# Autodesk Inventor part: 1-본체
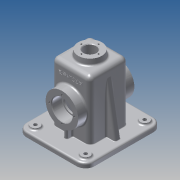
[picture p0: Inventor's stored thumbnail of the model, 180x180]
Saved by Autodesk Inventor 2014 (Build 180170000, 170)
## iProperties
Created: 2015-12
Part Number: 1-본체
Material: 알루미늄 6061
Document SubType Name: Modeling
Designer: Administrator
Density: 2.71 g/cm^3
Appearance: 알루미늄 - 평지
Mass: 803.266 g
Surface Area: 909.178 cm^2
Volume: 296.408 cm^3
Author: Administrator
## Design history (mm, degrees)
sketch "스케치1"
  geometry: L1 (-50, -57.5)-(50, -57.5); L2 (65, -42.5)-(65, 42.5); L3 (50, 57.5)-(-50, 57.5); L4 (-65, 42.5)-(-65, -42.5); A1 r 15 centre (-50, 42.5) between (-50, 57.5) and (-65, 42.5); A2 r 15 centre (-50, -42.5) between (-65, -42.5) and (-50, -57.5); A3 r 15 centre (50, -42.5) between (50, -57.5) and (65, -42.5); A4 r 15 centre (50, 42.5) between (65, 42.5) and (50, 57.5); 7 further points
  constraints: 8 end point, 8 point on circle, 8 point on line, 8 tangent, 4 centre point, 3 equal radius, 2 midpoint, 2 parallel, 1 horizontal, 1 horizontal alignment, 1 perpendicular, 1 vertical alignment
  dimensions: "d0" = 130 distance of point (-65, 57.5) point (65, 57.5); "d1" = 115 distance of point (65, 57.5) point (65, -57.5); "d4" = 15 radius of A1
extrude "돌출1" new body sketch "스케치1" distance "d2" = 8; taper "d3" = 0 deg
sketch "스케치2"
  geometry: L1 (50, 57.5)-(-50, 57.5) reference; L2 (-65, 42.5)-(-65, -42.5) reference; L3 (-50, -57.5)-(50, -57.5) reference; L4 (65, -42.5)-(65, 42.5) reference; L5 (-50, 52.5)-(50, 52.5); L6 (60, 42.5)-(60, -42.5); L7 (50, -52.5)-(-50, -52.5); L8 (-60, -42.5)-(-60, 42.5); A1 r 15 centre (-50, 42.5) between (-50, 57.5) and (-65, 42.5) reference; A2 r 15 centre (-50, -42.5) between (-65, -42.5) and (-50, -57.5) reference; A3 r 15 centre (50, -42.5) between (50, -57.5) and (65, -42.5) reference; A4 r 15 centre (50, 42.5) between (65, 42.5) and (50, 57.5) reference; A5 r 10 centre (50, 42.5) between (60, 42.5) and (50, 52.5); A6 r 10 centre (50, -42.5) between (50, -52.5) and (60, -42.5); A7 r 10 centre (-50, -42.5) between (-60, -42.5) and (-50, -52.5); A8 r 10 centre (-50, 42.5) between (-50, 52.5) and (-60, 42.5); 1 further point
  constraints: 8 end point, 8 point on circle, 4 centre point, 7 other
  dimensions: "d5" = 5 distance between parallel lines of L2 L8
extrude "돌출2" join sketch "스케치2" distance "d6" = 2; taper "d7" = 0 deg
sketch "스케치3"
  geometry: L1 (50, 57.5)-(-50, 57.5) reference; L2 (65, -42.5)-(65, 42.5) reference; C1 r 7.5 at (-50, 42.5); C2 r 7.5 at (50, 42.5); C3 r 7.5 at (-50, -42.5); C4 r 7.5 at (50, -42.5); A1 r 15 centre (-50, 42.5) between (-50, 57.5) and (-65, 42.5) reference; 1 further point
  constraints: 4 centre point, 1 coincident, 1 horizontal, 1 vertical, 6 other
  dimensions: "d8" = 15 diameter of C1; "d11" = 100 distance of C1.centre C2.centre; "d14" = 85 distance of C1.centre C3.centre
extrude "돌출3" join sketch "스케치3" distance "d17" = 3; taper "d18" = 0 deg
hole "구멍1" diameter "d21" = 6; stored, may be unused: countersink angle "d25" = 90 deg, drill point angle "d27" = 118 deg; dims "d19" = 10, "d20" = 10, "d22" = 6, "d23" = 4, "d24" = 2, "d26" = 8
hole "구멍2" diameter "d30" = 6; stored, may be unused: countersink angle "d34" = 90 deg, drill point angle "d36" = 118 deg; dims "d28" = 10, "d29" = 10, "d31" = 6, "d32" = 4, "d33" = 2, "d35" = 8
hole "구멍3" diameter "d39" = 6; stored, may be unused: countersink angle "d43" = 90 deg, drill point angle "d45" = 118 deg; dims "d37" = 10, "d38" = 10, "d40" = 6, "d41" = 4, "d42" = 2, "d44" = 8
hole "구멍4" diameter "d48" = 6; stored, may be unused: countersink angle "d52" = 90 deg, drill point angle "d54" = 118 deg; dims "d46" = 10, "d47" = 10, "d49" = 6, "d50" = 4, "d51" = 2, "d53" = 8
sketch "스케치4"
  geometry: L1 (-32.5, -32.5)-(32.5, -32.5); L2 (32.5, -32.5)-(32.5, 32.5); L3 (32.5, 32.5)-(-32.5, 32.5); L4 (-32.5, 32.5)-(-32.5, -32.5); L5 (-32.5, -32.5)-(32.5, 32.5); L6 (32.5, -32.5)-(-32.5, 32.5); 1 further point
  constraints: 12 end point, 2 midpoint, 2 parallel, 1 horizontal, 1 perpendicular
  dimensions: "d55" = 65 distance of L3.end L2.end; "d56" = 65 distance of L2.end L1.end
extrude "돌출4" join sketch "스케치4" distance "d57" = 100; taper "d58" = 0 deg
node "작업 평면1"
sketch "스케치5"
  geometry: C1 r 20 at (0, 0); 1 further point
  constraints: 1 centre point, 1 coincident
  dimensions: "d59" = 40 diameter of C1
extrude "돌출5" join sketch "스케치5" distance "d60" = 10; taper "d61" = 5 deg
sketch "스케치6"
  geometry: L1 (-100, 0)-(-100, 65) reference; L2 (10, 75)-(10, -10) reference; C1 r 27.5 at (-45, 32.5); 2 further points
  constraints: 1 centre point, 1 horizontal alignment, 1 midpoint
  dimensions: "d62" = 55 diameter of C1; "d63" = 55 distance from line of L2 C1.centre
extrude "돌출6" join sketch "스케치6" distance "d64" = 15; taper "d65" = 0 deg
hole "구멍5" diameter "d68" = 30; stored, may be unused: countersink angle "d72" = 90 deg, drill point angle "d74" = 118 deg; dims "d66" = 10, "d67" = 10, "d69" = 6, "d70" = 35, "d71" = 17, "d73" = 8
sketch "스케치7"
  geometry: C1 r 17.5 at (0, 0) reference; 2 further points
  constraints: 1 horizontal alignment
  dimensions: "d75" = 21 distance of C1.centre point (-21, 0)
hole "구멍6" sketch "스케치7" at (-21, 0) diameter "d76" = 3.242; stored, may be unused: countersink angle "d80" = 90 deg, drill point angle "d82" = 118 deg; dims "d77" = 8, "d78" = 35, "d79" = 17, "d81" = 10
hole "구멍7" diameter "d88" = 21; stored, may be unused: countersink angle "d92" = 90 deg, drill point angle "d94" = 118 deg; dims "d89" = 8, "d90" = 35, "d91" = 17, "d93" = 10, "d142" = 10, "d143" = 10
sketch "스케치9"
  geometry: L1 (-57.5, 0)-(-57.5, 8) reference; L2 (-57.5, 8)-(-32.5, 8) reference; L3 (-32.5, 8)-(-32.5, 108) reference; L4 (-32.5, 108)-(-20.875, 108) reference; L5 (-10.5, -2)-(-52.5, -2) reference; L6 (-52.5, -2)-(-52.5, 0) reference; L7 (-52.5, 0)-(-57.5, 0) reference; L8 (57.5, 8)-(57.5, 0) reference; L9 (57.5, 0)-(52.5, 0) reference; L10 (52.5, 0)-(52.5, -2) reference; L11 (20.875, 108)-(32.5, 108) reference; L12 (32.5, 108)-(32.5, 8) reference; L13 (32.5, 8)-(57.5, 8) reference; L14 (-32.5, 93.069)-(-47.5, 8); L15 (-20.875, 108)-(-20, 118) reference; L16 (-20, 118)-(-10.5, 118) reference; L17 (20, 118)-(20.875, 108) reference; L18 (-10.5, 118)-(-10.5, 63.712) reference; L19 (-10.5, 42.288)-(-10.5, -2) reference; L20 (52.5, -2)-(10.5, -2) reference; L21 (10.5, -2)-(10.5, 42.288) reference; L22 (10.5, 63.712)-(10.5, 118) reference; L23 (10.5, 118)-(20, 118) reference; A1 r 15 centre (0, 53) between (-10.5, 63.712) and (-10.5, 42.288) reference; A2 r 15 centre (0, 53) between (10.5, 42.288) and (10.5, 63.712) reference; 1 further point
  constraints: 2 end point, 2 point on line
  dimensions: "d107" = 10 distance from line of L14.end L1; "d109" = 10 deg angle of L14 L1
feature "리브1" sketch "스케치9" dims "d110" = 1, "d111" = 10, "d112" = 0, "d113" = 0, "d114" = 1, "d115" = 1
sketch "스케치10"
  geometry: L1 (-27.5, -27.5)-(27.5, -27.5); L2 (27.5, -27.5)-(27.5, 27.5); L3 (27.5, 27.5)-(-27.5, 27.5); L4 (-27.5, 27.5)-(-27.5, -27.5); L5 (-27.5, -27.5)-(27.5, 27.5); L6 (27.5, -27.5)-(-27.5, 27.5); C1 r 10.5 at (0, 0) reference
  constraints: 12 end point, 2 midpoint, 2 parallel, 1 horizontal, 1 perpendicular
  dimensions: "d116" = 55 distance of L3.end L2.end; "d117" = 55 distance of L2.end L1.end
extrude "돌출7" cut sketch "스케치10" distance "d118" = 105; taper "d119" = 0 deg
sketch "스케치11"
  geometry: L1 (32.5, 80.5)-(47.5, 80.5) reference; L2 (47.5, 80.5)-(47.5, 75.621) reference; L3 (47.5, 75.621)-(37.5, 75.621) reference; L4 (37.5, 75.621)-(36.526, 74) reference; L5 (36.526, 74)-(37.5, 72.379) reference; L6 (37.5, 72.379)-(47.5, 72.379) reference; L7 (47.5, 72.379)-(47.5, 70.5) reference; L8 (47.5, 70.5)-(30.5, 70.5) reference; L9 (30.5, 70.5)-(30.5, 68) reference; L10 (30.5, 68)-(27.5, 68) reference; L11 (27.5, 68)-(27.5, 103) reference; L12 (27.5, 103)-(10.5, 103) reference; L13 (20.875, 108)-(32.5, 108) reference; L14 (32.5, 108)-(32.5, 80.5) reference; L15 (47.5, 25.5)-(32.5, 25.5) reference; L16 (32.5, 25.5)-(32.5, 8) reference; L17 (32.5, 8)-(65, 8) reference; L18 (65, 8)-(65, 0) reference; L19 (65, 0)-(60, 0) reference; L20 (60, 0)-(60, -2) reference; L21 (60, -2)-(27.5, -2) reference; L22 (27.5, -2)-(27.5, 38) reference; L23 (27.5, 38)-(30.5, 38) reference; L24 (30.5, 38)-(30.5, 35.5) reference; L25 (30.5, 35.5)-(47.5, 35.5) reference; L26 (47.5, 35.5)-(47.5, 33.621) reference; L27 (47.5, 33.621)-(37.5, 33.621) reference; L28 (37.5, 33.621)-(36.526, 32) reference; L29 (36.526, 32)-(37.5, 30.379) reference; L30 (37.5, 30.379)-(47.5, 30.379) reference; L31 (47.5, 30.379)-(47.5, 25.5) reference; L32 (-47.5, 80.5)-(-32.5, 80.5) reference; L33 (-32.5, 80.5)-(-32.5, 108) reference; L34 (-32.5, 108)-(-20.875, 108) reference; L35 (-10.5, 103)-(-27.5, 103) reference; L36 (-27.5, 103)-(-27.5, 68) reference; L37 (-27.5, 68)-(-30.5, 68) reference; L38 (-30.5, 68)-(-30.5, 70.5) reference; L39 (-30.5, 70.5)-(-47.5, 70.5) reference; L40 (-47.5, 70.5)-(-47.5, 72.379) reference; L41 (-47.5, 72.379)-(-37.5, 72.379) reference; L42 (-37.5, 72.379)-(-36.526, 74) reference; L43 (-36.526, 74)-(-37.5, 75.621) reference; L44 (-37.5, 75.621)-(-47.5, 75.621) reference; L45 (-47.5, 75.621)-(-47.5, 80.5) reference; L46 (-32.5, 25.5)-(-47.5, 25.5) reference; L47 (-47.5, 25.5)-(-47.5, 30.379) reference; L48 (-47.5, 30.379)-(-37.5, 30.379) reference; L49 (-37.5, 30.379)-(-36.526, 32) reference; L50 (-36.526, 32)-(-37.5, 33.621) reference; L51 (-37.5, 33.621)-(-47.5, 33.621) reference; L52 (-47.5, 33.621)-(-47.5, 35.5) reference; L53 (-47.5, 35.5)-(-30.5, 35.5) reference; L54 (-30.5, 35.5)-(-30.5, 38) reference; L55 (-30.5, 38)-(-27.5, 38) reference; L56 (-27.5, 38)-(-27.5, -2) reference; L57 (-27.5, -2)-(-60, -2) reference; L58 (-60, -2)-(-60, 0) reference; L59 (-60, 0)-(-65, 0) reference; L60 (-65, 0)-(-65, 8) reference; L61 (-65, 8)-(-32.5, 8) reference; L62 (-32.5, 8)-(-32.5, 25.5) reference; L63 (-42.5, 25.5)-(-42.5, 8); L64 (-20.875, 108)-(-20, 118) reference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; 1 further point
  constraints: 2 end point, 2 point on line, 1 perpendicular
  dimensions: "d120" = 15 distance between parallel lines of L56 L63
feature "리브2" sketch "스케치11" dims "d122" = 1, "d123" = 6, "d124" = 0, "d125" = 0, "d126" = 1, "d127" = 1
fillet "모깎기1" dims "d128" = 8
fillet "모깎기2" dims "d129" = 0.3
chamfer "모따기1" distance "d130" = 1; stored, may be unused: second distance "d131" = 2, angle "d132" = 45 deg
fillet "모깎기3" dims "d133" = 3
fillet "모깎기4" dims "d134" = 3
fillet "모깎기5" dims "d135" = 1
fillet "모깎기6" dims "d136" = 3
sketch "스케치12"
  geometry: L1 (0, -8)-(91, -8) reference; L2 (-18, 4.5)-(-18, 44.5) reference; 2 further points
  constraints: 1 other
  dimensions: "d138" = 32.5 distance from line of point (8, 24.5) L1; "d155" = 26 distance from line of point (8, 24.5) L2
feature "엠보싱1" sketch "스케치12" dims "d139" = 0.5, "d140" = 0
sketch "스케치13"
  geometry: C1 r 10.5 at (0, 0) reference; 1 further point
  constraints: 1 vertical alignment
  dimensions: "d144" = 14.5 distance of C1.centre point (0, 14.5)
hole "구멍9" sketch "스케치13" at (0, 14.5) diameter "d145" = 2.459; stored, may be unused: countersink angle "d149" = 90 deg, drill point angle "d151" = 118 deg; dims "d146" = 7, "d147" = 4, "d148" = 2, "d150" = 9
node "솔리드1"
pattern_circular "원형 패턴1" dims angle "d84" = 360 deg
mirror "대칭1"
mirror "대칭2"
mirror "대칭3"
pattern_circular "원형 패턴3" dims angle "d153" = 360 deg
node "절단 모서리 투영1"
node "절단 모서리 투영2"
